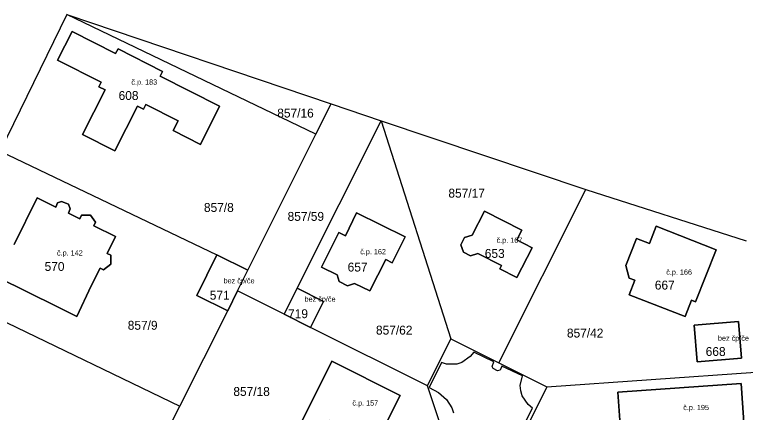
# Model space of a CAD drawing. Extents: x -887272 to -880188, y -1026687 to -1021896.
# Drawn here: x -886389.5 to -886250.1, y -1024275.2 to -1024199.3 of the extents above; entities that cross this region are included whole.
import ezdxf

# ---------------------------------------------------------------- set-up
doc = ezdxf.new("R2010")
doc.units = 0
for name, color, linetype in [('Definiční body', 7, 'Continuous'), ('Hranice parcel', 7, 'Continuous'), ('Parcelní čísla', 7, 'Continuous'), ('Polygon budovy', 7, 'Continuous')]:
    doc.layers.add(name, color=color, linetype=linetype)

msp = doc.modelspace()

# ---------------------------------------------------------------- linework, layer by layer
at = {"layer": 'Hranice parcel'}
for p, q in [((-886379.52, -1024199.32), (-886392.22, -1024225.37)), ((-886332.05, -1024222.15), (-886379.52, -1024199.32)), ((-886379.52, -1024199.32), (-886329.14, -1024216.34)), ((-886332.05, -1024222.15), (-886329.14, -1024216.34)), ((-886329.14, -1024216.34), (-886319.58, -1024219.56)), ((-886335.61, -1024251.54), (-886319.58, -1024219.56)), ((-886319.58, -1024219.56), (-886306.31, -1024261.2)), ((-886319.58, -1024219.56), (-886280.58, -1024232.7)), ((-886345.03, -1024248.08), (-886332.05, -1024222.15)), ((-886392.22, -1024225.37), (-886350.92, -1024245.18)), ((-886297.14, -1024265.79), (-886280.58, -1024232.7)), ((-886280.58, -1024232.7), (-886250, -1024242.5)), ((-886350.92, -1024245.18), (-886345.03, -1024248.08)), ((-886347, -1024252.02), (-886345.03, -1024248.08)), ((-886404.92, -1024251.42), (-886358, -1024274.01)), ((-886347, -1024252.02), (-886348.82, -1024255.84)), ((-886338.08, -1024256.48), (-886347, -1024252.02)), ((-886338.08, -1024256.48), (-886335.61, -1024251.54)), ((-886358, -1024274.01), (-886348.82, -1024255.84)), ((-886333.06, -1024258.99), (-886338.08, -1024256.48)), ((-886310.78, -1024270.14), (-886333.06, -1024258.99)), ((-886310.78, -1024270.14), (-886306.31, -1024261.2)), ((-886306.31, -1024261.2), (-886297.14, -1024265.79)), ((-886297.14, -1024265.79), (-886287.98, -1024270.37)), ((-886287.98, -1024270.37), (-886248.19, -1024267.54)), ((-886287.98, -1024270.37), (-886292.45, -1024279.32)), ((-886360.02, -1024278.04), (-886358, -1024274.01))]:
    msp.add_line(p, q, dxfattribs=at)
for points in [[(-886381.28, -1024208), (-886378.53, -1024202.56), (-886370.22, -1024206.77), (-886369.76, -1024205.87), (-886361.3, -1024210.15), (-886361.75, -1024211.05), (-886350.44, -1024216.77), (-886354.02, -1024224.11), (-886359.26, -1024221.44), (-886358.31, -1024219.58), (-886364.47, -1024216.46), (-886364.93, -1024217.37), (-886366.07, -1024216.79), (-886370.38, -1024225.3), (-886376.54, -1024222.18), (-886372.24, -1024213.69), (-886373.42, -1024213.09), (-886372.97, -1024212.2), (-886381.28, -1024208)], [(-886389.57, -1024243.18), (-886385.19, -1024234.27), (-886381.65, -1024236.03), (-886381.31, -1024235.21), (-886380.51, -1024234.96), (-886379.22, -1024235.51), (-886378.88, -1024236.39), (-886379.23, -1024237.22), (-886377.05, -1024238.3)], [(-886377.05, -1024238.3), (-886376.73, -1024237.59), (-886375.04, -1024237.6), (-886374.03, -1024238.92), (-886374.38, -1024239.62), (-886370.27, -1024241.66), (-886371.84, -1024244.9), (-886371.11, -1024245.23), (-886371.12, -1024246.96), (-886372.53, -1024248.01), (-886373.18, -1024247.68), (-886374.86, -1024251.05), (-886377.64, -1024256.89), (-886381.46, -1024255.02), (-886392.68, -1024249.51)], [(-886327.99, -1024248.97), (-886330.95, -1024247.51), (-886327.67, -1024240.88), (-886326.41, -1024241.5), (-886324.27, -1024237.17), (-886315.03, -1024241.74), (-886317.47, -1024246.68), (-886318.73, -1024246.05), (-886321.73, -1024252.05), (-886324.69, -1024250.6), (-886326.03, -1024251.04), (-886327.57, -1024250.27), (-886327.99, -1024248.97)], [(-886296.97, -1024247.82), (-886296.63, -1024247.17), (-886301.13, -1024244.89), (-886302.55, -1024245.37), (-886303.9, -1024244.66), (-886304.37, -1024243.23), (-886303.69, -1024241.86), (-886302.25, -1024241.41), (-886299.91, -1024236.8), (-886292.76, -1024240.44), (-886293.71, -1024242.31), (-886290.81, -1024243.79), (-886293.71, -1024249.5), (-886296.97, -1024247.82)], [(-886260.4, -1024253.83), (-886261.61, -1024256.91), (-886272.29, -1024252.76), (-886271.23, -1024250.01), (-886272.28, -1024249.6), (-886272.97, -1024247.22), (-886270.89, -1024242.01), (-886268.45, -1024242.97), (-886267.15, -1024239.67), (-886255.7, -1024244.19), (-886259.63, -1024254.14), (-886260.4, -1024253.83)], [(-886348.82, -1024255.84), (-886354.75, -1024252.91), (-886350.92, -1024245.18)], [(-886335.61, -1024251.54), (-886330.61, -1024254.05), (-886333.06, -1024258.99)], [(-886259.33, -1024265.57), (-886259.93, -1024258.56), (-886251.47, -1024257.87), (-886250.9, -1024264.89), (-886259.33, -1024265.57)], [(-886293.1, -1024279.08), (-886290.74, -1024274.38), (-886291.58, -1024273.7), (-886292.69, -1024272.06), (-886292.96, -1024271.12), (-886293.06, -1024270.11), (-886292.65, -1024268.27), (-886296.56, -1024266.37), (-886296.89, -1024267.15), (-886297.4, -1024267.31), (-886298.26, -1024266.86), (-886298.44, -1024266.43), (-886298.1, -1024265.57), (-886301.95, -1024263.72), (-886302.59, -1024264.54), (-886304.19, -1024265.71), (-886305.14, -1024266.04), (-886307.11, -1024266.04), (-886308.09, -1024265.73), (-886310.42, -1024270.48), (-886308.65, -1024271.41), (-886307.15, -1024272.75), (-886306.11, -1024274.37), (-886305.8, -1024275.33)], [(-886327.06, -1024277.99), (-886329.53, -1024276.75), (-886330.51, -1024278.72), (-886334.6, -1024276.67), (-886328.98, -1024265.47), (-886315.96, -1024271.99), (-886321.98, -1024284.02), (-886328.46, -1024280.78), (-886327.06, -1024277.99)], [(-886318.44, -1024298.85), (-886308.1, -1024278.19), (-886310.78, -1024270.14)], [(-886273.81, -1024280.61), (-886274.02, -1024277.62), (-886274.46, -1024271.34), (-886250.94, -1024269.69), (-886250.29, -1024278.96), (-886256.07, -1024279.36), (-886255.67, -1024285.12), (-886262.56, -1024285.6), (-886265.71, -1024285.82), (-886266.11, -1024280.07), (-886273.81, -1024280.61)]]:
    msp.add_lwpolyline(points, dxfattribs=at)
at = {"layer": 'Polygon budovy'}
for points in [[(-886378.53, -1024202.56), (-886381.28, -1024208), (-886372.97, -1024212.2), (-886373.42, -1024213.09), (-886372.24, -1024213.69), (-886376.54, -1024222.18), (-886370.38, -1024225.3), (-886366.07, -1024216.79), (-886364.93, -1024217.37), (-886364.47, -1024216.46), (-886358.31, -1024219.58), (-886359.26, -1024221.44), (-886354.02, -1024224.11), (-886350.44, -1024216.77), (-886361.75, -1024211.05), (-886361.3, -1024210.15), (-886369.76, -1024205.87), (-886370.22, -1024206.77)], [(-886324.27, -1024237.17), (-886326.41, -1024241.5), (-886327.67, -1024240.88), (-886330.95, -1024247.51), (-886327.99, -1024248.97), (-886327.57, -1024250.27), (-886326.03, -1024251.04), (-886324.69, -1024250.6), (-886321.73, -1024252.05), (-886318.73, -1024246.05), (-886317.47, -1024246.68), (-886315.03, -1024241.74)], [(-886299.91, -1024236.8), (-886302.25, -1024241.41), (-886303.69, -1024241.86), (-886304.37, -1024243.23), (-886303.9, -1024244.66), (-886302.55, -1024245.37), (-886301.13, -1024244.89), (-886296.63, -1024247.17), (-886296.97, -1024247.82), (-886293.71, -1024249.5), (-886290.81, -1024243.79), (-886293.71, -1024242.31), (-886292.76, -1024240.44)], [(-886267.15, -1024239.67), (-886268.45, -1024242.97), (-886270.89, -1024242.01), (-886272.97, -1024247.22), (-886272.28, -1024249.6), (-886271.23, -1024250.01), (-886272.29, -1024252.76), (-886261.61, -1024256.91), (-886260.4, -1024253.83), (-886259.63, -1024254.14), (-886255.7, -1024244.19)], [(-886350.92, -1024245.18), (-886354.75, -1024252.91), (-886348.82, -1024255.84), (-886347, -1024252.02), (-886345.03, -1024248.08)], [(-886338.08, -1024256.48), (-886333.06, -1024258.99), (-886330.61, -1024254.05), (-886335.61, -1024251.54)], [(-886259.93, -1024258.56), (-886259.33, -1024265.57), (-886250.9, -1024264.89), (-886251.47, -1024257.87)], [(-886328.98, -1024265.47), (-886334.6, -1024276.67), (-886330.51, -1024278.72), (-886329.53, -1024276.75), (-886327.06, -1024277.99), (-886328.46, -1024280.78), (-886321.98, -1024284.02), (-886315.96, -1024271.99)], [(-886256.07, -1024279.36), (-886250.29, -1024278.96), (-886250.94, -1024269.69), (-886274.46, -1024271.34), (-886274.02, -1024277.62), (-886273.81, -1024280.61), (-886266.11, -1024280.07), (-886265.71, -1024285.82), (-886262.56, -1024285.6), (-886255.67, -1024285.12)]]:
    msp.add_lwpolyline(points, close=True, dxfattribs=at)
msp.add_lwpolyline([(-886392.68, -1024249.51), (-886381.46, -1024255.02), (-886377.64, -1024256.89), (-886374.86, -1024251.05), (-886373.18, -1024247.68), (-886372.53, -1024248.01), (-886371.12, -1024246.96), (-886371.11, -1024245.23), (-886371.84, -1024244.9), (-886370.27, -1024241.66), (-886374.38, -1024239.62), (-886374.03, -1024238.92), (-886375.04, -1024237.6), (-886376.73, -1024237.59), (-886377.05, -1024238.3), (-886379.23, -1024237.22), (-886378.88, -1024236.39), (-886379.22, -1024235.51), (-886380.51, -1024234.96), (-886381.31, -1024235.21), (-886381.65, -1024236.03), (-886385.19, -1024234.27), (-886389.57, -1024243.18)], dxfattribs=at)

# ---------------------------------------------------------------- texts
at = {"layer": 'Definiční body'}
for s, p in [('č.p. 183', (-886367.21, -1024212.69)), ('č.p. 167', (-886297.59, -1024242.86)), ('č.p. 142', (-886381.4, -1024245.29)), ('č.p. 162', (-886323.59, -1024245.05)), ('č.p. 166', (-886265.24, -1024248.95)), ('bez čp/če', (-886349.64, -1024250.6)), ('bez čp/če', (-886334.2, -1024254.1)), ('bez čp/če', (-886255.38, -1024261.56)), ('č.p. 157', (-886325.07, -1024273.92)), ('č.p. 195', (-886262, -1024274.78))]:
    msp.add_text(s, height=1, dxfattribs=at).set_placement(p)
at = {"layer": 'Parcelní čísla'}
for s, p in [('608', (-886369.65, -1024215.61)), ('857/16', (-886339.4, -1024218.96)), ('857/17', (-886306.77, -1024234.24)), ('857/8', (-886353.38, -1024236.97)), ('857/59', (-886337.43, -1024238.67)), ('653', (-886299.83, -1024245.74)), ('570', (-886383.76, -1024248.22)), ('657', (-886325.98, -1024248.34)), ('667', (-886267.41, -1024251.78)), ('571', (-886352.27, -1024253.72)), ('719', (-886337.34, -1024257.24)), ('857/9', (-886367.91, -1024259.45)), ('857/62', (-886320.58, -1024260.37)), ('857/42', (-886284.17, -1024260.93)), ('668', (-886257.71, -1024264.45)), ('857/18', (-886347.77, -1024272.08))]:
    msp.add_text(s, height=1.7, dxfattribs=at).set_placement(p)

doc.saveas('drawing.dxf')
